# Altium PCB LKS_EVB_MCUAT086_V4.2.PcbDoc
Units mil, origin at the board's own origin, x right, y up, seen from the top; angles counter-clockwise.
Board outline 2625 x 1560 mil, 2 copper layers (Top Layer, Bottom Layer); 66 components, 80 nets, 250 pads, 95 vias.
Unrouted connection lines stored in the file: 34.
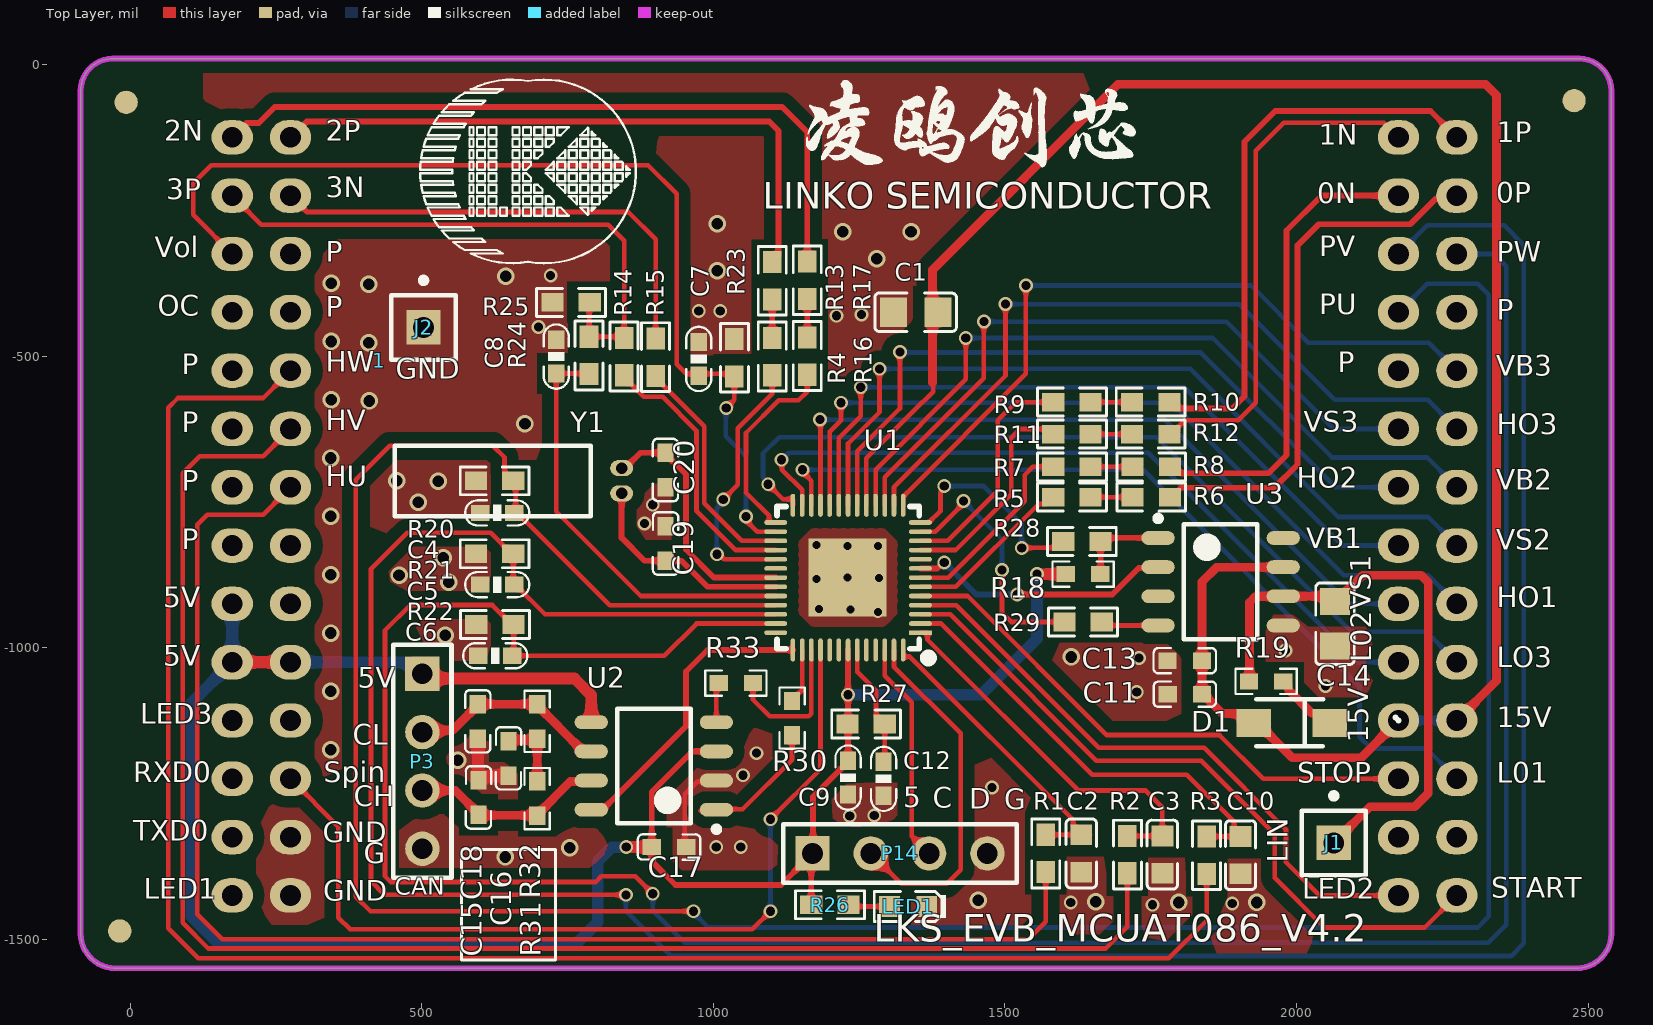
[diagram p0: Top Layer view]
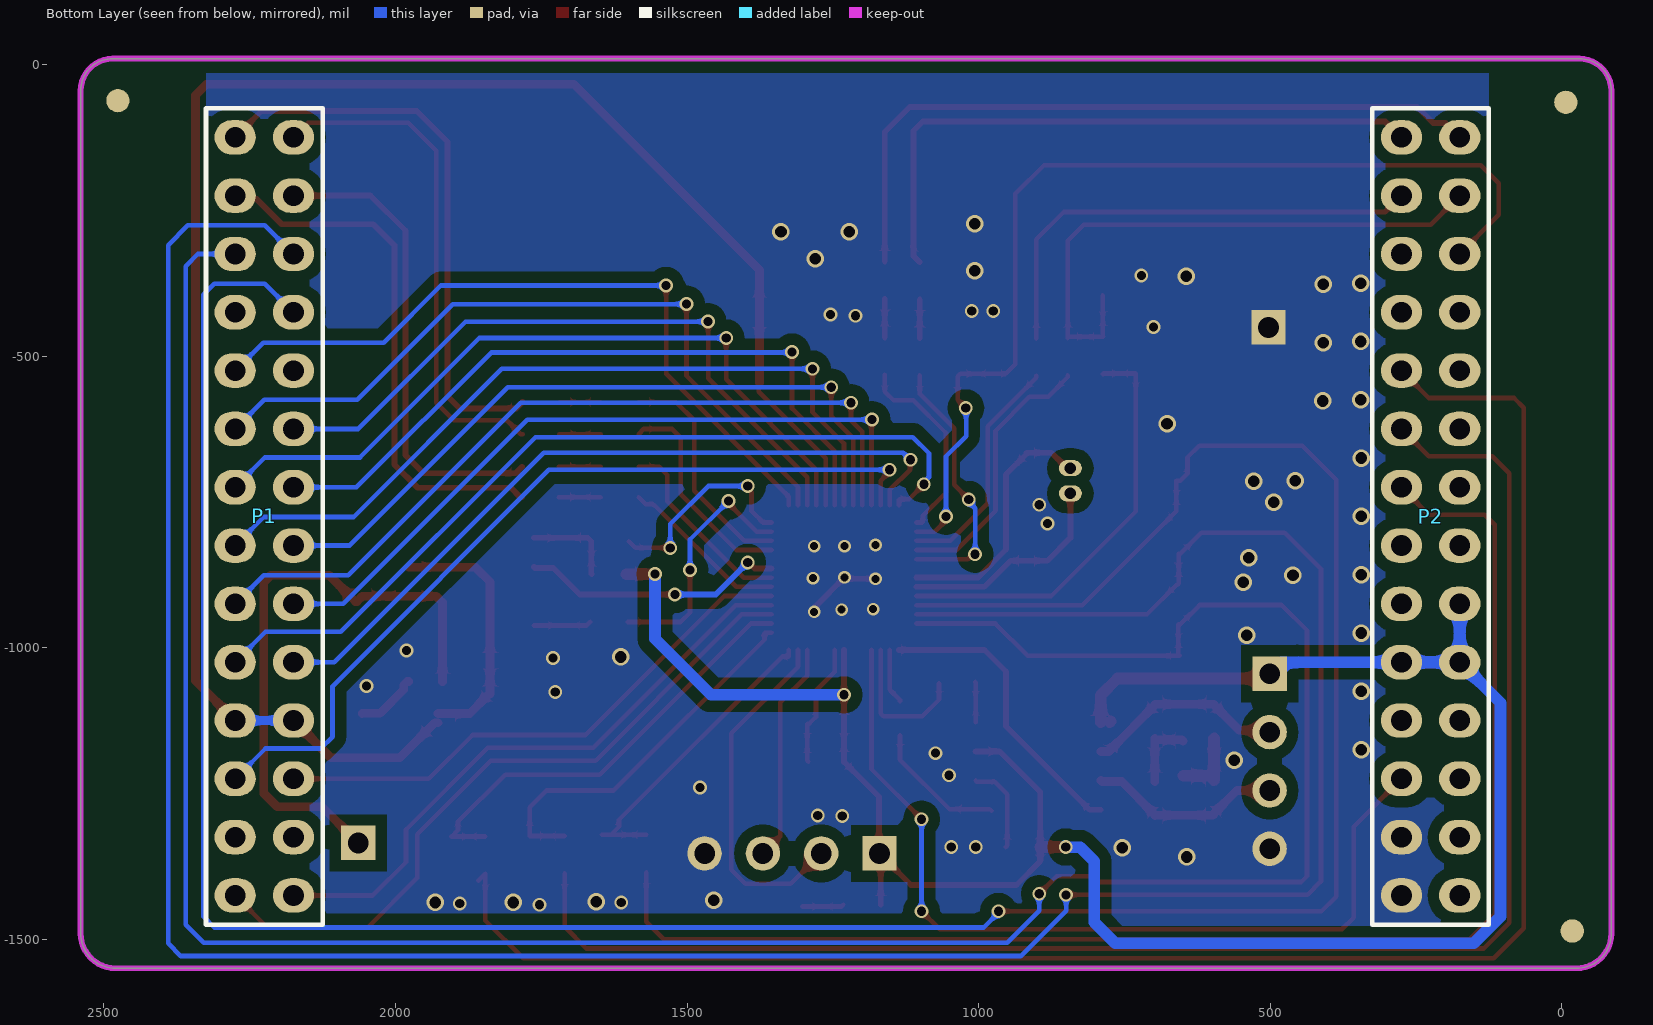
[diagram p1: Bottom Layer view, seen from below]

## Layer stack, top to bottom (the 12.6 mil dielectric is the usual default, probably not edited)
Top Solder: solder mask 0.4, Solder Resist, Dk 3.5
Top Layer: signal copper 1.4
Dielectric1: dielectric 12.6, FR-4, Dk 4.8
Bottom Layer: signal copper 1.4
Bottom Solder: solder mask 0.4, Solder Resist, Dk 3.5

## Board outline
-85,-1490 ccw(c-25,-1490) -25,-1550 2480,-1550 ccw(c2480,-1490) 2540,-1490 2540,-45 ccw(c2485,-45) 2485,10 -30,10 ccw(c-30,-45) -85,-45

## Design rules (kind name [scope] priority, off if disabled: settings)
Clearance Clearance_1 [InPolygon] p1: gap=20 ignorepadtopadclearanceinfootprint=FALSE except(0: Arc-Hole Track-Hole SMDPad-Hole THPad-Hole Via-Hole Fill-Hole Poly-Hole Region-Hole Text-Hole)
Clearance [All] p2: gap=0 ignorepadtopadclearanceinfootprint=FALSE
ComponentClearance [All] p1: gap=0 collisioncheckmode=3 verticalgap=0 showdistances=FALSE
FabricationTestpoint [(IsPad And (OnTopLayer Or OnBottomLayer))] p1: side=3 testpointundercomponent=TRUE minsize=40 maxsize=100 preferedsize=60 minholesize=0 maxholesize=40 preferedholesize=32 testpointgrid=1 allowsidetop=TRUE allowsidebottom=TRUE usegrid=TRUE gridtolerance=0.01
HoleSize [All] p1: absolutevalues=TRUE maxlimit=100 minlimit=0 maxpercent=80.000 minpercent=20.000
PolygonConnect [All] p1: connectstyle=Direct reliefconductorwidth=30 reliefentries=4 polygonreliefangle="90 Angle" airgapwidth=10
RoutingVias [All] p1: holewidth=12 width=20 viastyle="Through Hole" minholewidth=0 minwidth=10 maxholewidth=100 maxwidth=200
SilkToSolderMaskClearance SilkscreenOverComponentPads [IsPad] p1: minsilkscreentomaskgap=10 clearancetoexposedcopper=TRUE
SolderMaskExpansion [All] p1: expansion=4 istentingtop=FALSE
Width [All] p1: maxlimit=100 minlimit=7.87 preferedwidth=10
26 further rules are at their usual default settings.

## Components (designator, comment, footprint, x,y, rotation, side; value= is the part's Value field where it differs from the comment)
1 "LKS_sign" LKS_LOGO2 427,-508 r0 top
C1 "10uF/25V" 0805C 1347,-425 r180 top
C2 "10nF/16V" 0603C#1 1631,-1353 r270 top
C3 "10nF/16V" 0603C#1 1770,-1355 r270 top
C4 "1nF/16V" 0603C#2 629.41,-768.98 r180 top
C5 "1nF/16V" 0603C#2 629.41,-892 r180 top
C6 "1nF/16V" 0603C#2 626.05,-1014 r180 top
C7 "100nF/50V" 0603C#2 975,-504.95 r270 top
C8 "1nF/50V" 0603C#2 730.65,-500.91 r270 top
C9 "1uF/16V" 0603C#2 1231,-1223 r90 top
C10 "10nF/16V" 0603C#1 1904,-1356 r270 top
C11 "2.2uF/25V" "0603C _1" 1808.47,-1080 r180 top
C12 "100nF/50V" 0603C#2 1292,-1225 r270 top
C13 "100nF" "0603C _1" 1808.44,-1022.53 r180 top
C14 "1nF" 0805C 2066,-959 r270 top
C15 "30pF" "0603C _1" 597,-1257 r90 top
C16 "4.7nF/50V" "0603C _1" 649,-1190 r270 top
C17 "100nF" "0603C _1" 924,-1342 r180 top
C18 "30pF" "0603C _1" 596,-1126.47 r90 top
C19 "4.7nF/50V" "0603C _1" 918,-821.53 r90 top
C20 "4.7nF/50V" "0603C _1" 918,-695.47 r270 top
D1 "1N4148" SOD123 1992,-1129 r0 top
J1 "Socket" PIN1 2064,-1335 r0 top
J2 "Socket" PIN1 503,-451 r0 top
LED1 "LED" 0603D 1334,-1444 r0 top
P1 "Header 14X2A" "HDR 2X14 顶层" 2225,-775 r180 bottom locked
P2 "Header 14X2A" "HDR 2X14 顶层" 225,-775 r180 bottom locked
P3 "Header 4" HDR1X4 501,-1045 r270 top
P14 "Header 4" "HDR 1X4" 1170,-1353 r0 top
R1 "2K" 0603R 1570,-1353 r90 top value=K
R2 "2K" 0603R 1710,-1355 r90 top value=K
R3 "2K" 0603R 1846,-1356 r90 top value=K
R4 "20K" 0603R 1101,-501 r270 top value=K
R5 "20K" 0603R 1615,-742 r180 top value=K
R6 "20K" 0603R 1751,-742 r180 top value=K
R7 "20K" 0603R 1615,-690 r180 top value=K
R8 "20K" 0603R 1751,-690 r180 top value=K
R9 "20K" 0603R 1615,-579 r180 top value=K
R10 "20K" 0603R 1750,-579 r180 top value=K
R11 "20K" 0603R 1615,-634 r180 top value=K
R12 "20K" 0603R 1750,-634 r180 top value=K
R13 "20K" 0603R 1101,-371 r270 top value=K
R14 "1K" 0603R 847,-501 r270 top value=K
R15 "1K" 0603R 901,-502 r270 top value=K
R16 "20K" 0603R 1161,-500 r270 top value=K
R17 "20K" 0603R 1161,-370 r270 top value=K
R18 "10K" 0603R_1 1634,-874 r0 top value=K
R19 "1K" 0603R_1 1948,-1058 r180 top value=K
R20 "1K" 0603R 625,-713.95 r180 top value=K
R21 "1K" 0603R 625,-839 r180 top value=K
R22 "1K" 0603R 625.55,-960.32 r180 top value=K
R23 "1K" 0603R 1036,-503 r270 top value=K
R24 "1K" 0603R 786.65,-498.91 r90 top value=K
R25 "10R" 0603R 756,-408 r180 top value=K
R26 "3.3K" 0603R 1200,-1441 r180 top value=330
R27 "20K" 0603R 1262,-1131 r0 top value=K
R28 "10R" 0603R 1632,-818 r180 top value=K
R29 "10R" 0603R 1634,-956 r180 top value=K
R30 "10R" 0603R_1 1135,-1121 r270 top value=K
R31 "60R/1%" 0603R_1 698,-1259 r90 top value=K
R32 "60R/1%" 0603R_1 698,-1126.47 r90 top value=K
R33 "10R" 0603R_1 1038.51,-1061 r180 top value=K
U1 "LKS32AT086N8Q8" QFN52 1355.02,-974.49 r180 top
U2 "SIT1051T/3" SOP-8N 898,-1203 r180 top
U3 "SIT1027Q" SOP-8N 1870,-887 r0 top
Y1 "WTL3T45412LZ" DT-38 579,-714 r0 top

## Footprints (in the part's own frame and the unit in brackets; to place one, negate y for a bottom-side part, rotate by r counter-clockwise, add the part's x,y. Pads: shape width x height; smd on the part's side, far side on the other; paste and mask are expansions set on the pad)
0603C#1 [mm]
  rect 0.9x0.95 smd: 1(-0.813,0) 2(0.813,0)
  silkscreen extent -1.5,-0.66 1.5,0.66, body extent -0.8,-0.4 0.8,0.4, height 0.45
0603C#2 [mm] "电?"
  rect 0.8x0.7 smd: 1(-0.737,0) 2(0.738,0)
  silkscreen extent -1.4,-0.55 1.4,0.55, body extent -0.8,-0.41 0.8,0.41, height 0.81
"0603C _1" [mm]
  rect 0.8x0.7 smd: 1(-0.75,0) 2(0.75,0)
  silkscreen extent -1.36,-0.56 1.36,0.55, body extent -0.8,-0.41 0.8,0.41, height 0.81
0603D [mm]
  rect 0.9x0.9 smd: 1(-0.813,0) 2(0.813,0)
  silkscreen extent -1.47,-0.66 1.65,0.66
0603R [mil]
  rect 38x32 smd: 1(-32,0) 2(32,0)
  silkscreen extent -59,-24 59,24, body extent -31,-16 32,16, height 16
0603R_1 [mm]
  rect 0.8x0.7 smd: 1(-0.75,0) 2(0.75,0)
  silkscreen extent -1.33,-0.55 1.33,0.55, body extent -0.8,-0.4 0.8,0.4, height 0.4
0805C [mil]
  rect 46x51.18 smd: 1(-38,0) 2(38,0)
  silkscreen extent -70,-33 70,33, body extent -40,-25 38,25, height 22
DT-38 [mm] "CRYSTAL 晶?"
  oval 1x0.7 hole 0.5 paste+0 mask+0: 1(6.7,0.55) 2(6.7,-0.55)
  silkscreen extent -3.17,-1.55 5.36,1.52, body extent -3.2,-1.85 6.73,1.85, height 0.25
HDR1X4 [mm] "Connector; Header; 4 Position"
  rect 1.5x1.5 hole 0.9: 1(0,0)
  round 1.5 hole 0.9: 2(2.54,0) 3(5.08,0) 4(7.62,0)
  silkscreen extent -1.27,-1.27 8.89,1.27
"HDR 1X4" [mm] "排针-单 2.54"
  rect 1.5x1.5 hole 0.9: 1(0,0)
  round 1.5 hole 0.9: 2(2.54,0) 3(5.08,0) 4(7.62,0)
  silkscreen extent -1.27,-1.27 8.89,1.27, body extent -1.27,-1.27 8.89,1.27, height 8.5
"HDR 2X14 顶层" [mm] "双排针 2.54mm 顶层"
  oval 1.8x1.5 hole 0.9: 1(1.27,16.51) 2(1.27,13.97) 3(1.27,11.43) 4(1.27,8.89) 5(1.27,6.35) 6(1.27,3.81) 7(1.27,1.27) 8(1.27,-1.27) 9(1.27,-3.81) 10(1.27,-6.35) 11(1.27,-8.89) 12(1.27,-11.43) 13(1.27,-13.97) 14(1.27,-16.51) 15(-1.27,16.51) 16(-1.27,13.97) 17(-1.27,11.43) 18(-1.27,8.89) 19(-1.27,6.35) 20(-1.27,3.81) 21(-1.27,1.27) 22(-1.27,-1.27) 23(-1.27,-3.81) 24(-1.27,-6.35) 25(-1.27,-8.89) 26(-1.27,-11.43) 27(-1.27,-13.97) 28(-1.27,-16.51)
  silkscreen extent -2.54,-17.78 2.54,17.78, body extent -2.54,-17.78 2.54,17.78, height 8.5
LKS_LOGO2 [mil] "标?"
  silkscreen extent 70,167 440,482
PIN1 [mm] "Connector; Plug"
  rect 1.5x1.5 hole 0.9: 1(0,0)
  silkscreen extent -1.4,-1.4 1.4,2.17
QFN52 [mm]
  rect 3.4x3.4 smd: 0(3.175,-2.413)
  rect 1x0.2 smd: 1(0,0)
  oval 1x0.2 smd: 2(0,-0.4) 3(0,-0.8) 4(0,-1.2) 5(0,-1.6) 6(0,-2) 7(0,-2.4) 8(0,-2.8) 9(0,-3.2) 10(0,-3.6) 11(0,-4) 12(0,-4.4) 13(0,-4.8) 27(6.3,-4.8) 28(6.3,-4.4) 29(6.3,-4) 30(6.3,-3.6) 31(6.3,-3.2) 32(6.3,-2.8) 33(6.3,-2.4) 34(6.3,-2) 35(6.3,-1.6) 36(6.3,-1.2) 37(6.3,-0.8) 38(6.3,-0.4) 39(6.3,0)
  oval 0.2x1 smd: 14(0.75,-5.55) 15(1.15,-5.55) 16(1.55,-5.55) 17(1.95,-5.55) 18(2.35,-5.55) 19(2.75,-5.55) 20(3.15,-5.55) 21(3.55,-5.55) 22(3.95,-5.55) 23(4.35,-5.55) 24(4.75,-5.55) 25(5.15,-5.55) 26(5.55,-5.55) 40(5.55,0.75) 41(5.15,0.75) 42(4.75,0.75) 43(4.35,0.75) 44(3.95,0.75) 45(3.55,0.75) 46(3.15,0.75) 47(2.75,0.75) 48(2.35,0.75) 49(1.95,0.75) 50(1.55,0.75) 51(1.15,0.75) 52(0.75,0.75)
  silkscreen extent -0.46,-5.5 6.25,1.21
SOD123 [mm] "SOD-123; 2 Leads; Body 2.7 x 1.6 mm, (LxW)"
  rect 1.5x1.22 smd: 1(-1.65,0) 2(1.65,0)
  silkscreen extent -1.55,-1.03 1.38,1.02, body extent -1.93,-0.82 1.93,0.87, height 0.92
SOP-8N [mm]
  oval 1.45x0.6 smd: 1(-2.725,1.905) 2(-2.725,0.635) 3(-2.725,-0.635) 4(-2.725,-1.905) 5(2.725,-1.905) 6(2.725,-0.635) 7(2.725,0.635) 8(2.725,1.905)
  silkscreen extent -2.85,-2.5 1.6,2.88, body extent -2,-2.5 2,2.5, height 1.7

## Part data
C1 C11 C13 C14 C15 C16 C17 C18 C19 C20: library part Capacitor, "Capacitor --贴片电容"
C2 C3 C4 C5 C6 C10: library part CAP, "Capacitor"
C7 C8 C9 C12: library part C, "Capacitor"
D1: library part Diode, "Default Diode", PackageDocument=Sep-1996
LED1: "LED_Light"
P1 P2: "Header, 14-Pin, Dual row"
P3 P14: "Header, 4-Pin"
R1 R2 R3 R4 R5 R6 R7 R8 R9 R10 R11 R12 R13 R14 R15 R16 R17 R18 R19 R20 R21 R22 R23 R24 R25 R26 R27 R28 R29 R30 R31 R32 R33: library part Res, "Resistor"
U1: "车规芯片"
U2: "SIT芯力特CAN芯片  sop-8"
U3: library part SIT1021T, "SIT芯力特LIN芯片  SOP-8"
Y1: library part CMP-27762-006068-1, "CRYSTAL 32.7680KHZ 12.5PF TH", Case/Package=Radial, ESR (Equivalent Series Resistance)=50kR, Frequency=32.768kHz, Frequency Stability=-0.034ppm, Frequency Tolerance=20ppm, Load Capacitance=12.5pF, Manufacturer=Abracon, Manufacturer Part Number=AB26TRB-32.768KHZ-T, Max Operating Temperature=85°C, Min Operating Temperature=-40°C, Operating Frequency="32.768 kHz", Package Quantity=500

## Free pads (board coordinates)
  round 40 all layers, no hole: 5(-18,-1486) 5(-7,-65) 5(2476,-62)

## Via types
v1: diameter 23.62, hole 15.75, Top Layer to Bottom Layer, 52 vias
v2: diameter 30, hole 20, Top Layer to Bottom Layer, 34 vias
v3: diameter 21.65, hole 13.78, Top Layer to Bottom Layer, 9 vias

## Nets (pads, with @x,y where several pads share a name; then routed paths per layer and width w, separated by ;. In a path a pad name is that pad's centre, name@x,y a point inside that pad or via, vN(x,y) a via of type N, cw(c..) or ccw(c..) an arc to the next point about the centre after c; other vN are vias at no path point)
+5V: C9.2 C17.2 P2.9 P2.10 P2.24 P3.1 P14.1 R18.1 R26.2 R27.1 U1.46 U2.3 U2.5 | length 3860.5
  Top Layer w10: U2.3 964,-1178 894.47,-1247.53 C17.2 894.47,-1366.47 935,-1407 1116,-1407 P14.1 ; R26.2 1168,-1355 P14.1 ; U1.46 v1(1231,-1081) C9.2 1231,-1195.91 1171,-1255.91 1171,-1352 P14.1
  Top Layer w20: P2.10 P2.24 P2.24@275,-1018 ; P3.1 509,-1053 762,-1053 790.72,-1081.72 U2.5 ; U2.5@773.29,-1126.33 U2.5@774.96,-1128 ; v1(850.56,-1341.86) v1(850.56,-1341.86) 894.4,-1341.93 C17.2 ; v1(1555,-874) R18.1
  Bottom Layer w20: P2.9 P2.10 ; P3.1 481,-1025 P2.24 P2.10 ; v1@851.26,-1340.19 851.26,-1341.17 849.87,-1342.55 826.01,-1342.55 802,-1366.57 802,-1471 766,-1507 151,-1507 105,-1461 105,-1095 P2.10 ; v1(1231,-1081) 1459,-1081 1555,-985 v1(1555,-874)
+15V: C1.1 C11.1 C13.1 D1.1 P1.11 P1.25 U1.18 U3.7 | length 3502.8
  Top Layer w8: U1.18 1262.5,-675.5 1343,-595 1377,-561 1377,-545.65
  Top Layer w15: 1376,-545.65 1376,-352 1694,-34 2324,-34 2343,-53 2343,-1057 P1.25 ; D1.1@1927,-1113 1872.97,-1113 1839.97,-1080 C11.1 1838,-887 1863,-862 U3.7 ; D1.1 1932.55,-1129 1992.55,-1189 2111,-1189 P1.11
  Bottom Layer w15: P1.11 P1.25
CAN_RX: R33.1 U1.42 | length 251.5
  Top Layer w8: R33.1 1068.04,-1089.54 1096.5,-1118 1163.32,-1118 1168.01,-1113.31 U1.42
CAN_TX: R30.1 U1.41 | length 94.6
  Top Layer w8: R30.1 1135,-1089.5 1152.26,-1072.24 U1.41
CANH: C15.1 P3.3 R31.1 U2.7 | length 335.1
  Top Layer w15: P3.3 557.44,-1245 597,-1284.56 C15.1 598,-1287.53 697,-1287.53 R31.1 698,-1286.56 754.91,-1229.65 789.07,-1229.65 U2.7
CANL: C18.2 P3.2 R32.2 U2.6 | length 350
  Top Layer w15: P3.2@501,-1149 P3.2 504.11,-1141.89 553.03,-1141.89 596,-1098.91 C18.2 R32.2 698,-1098.91 772.33,-1173.25 772.33,-1174.02 776.32,-1178 U2.6
GND: C1.2 C2.2 C3.2 C4.2 C5.2 C6.2 C7.1 C8.1 C9.1 C10.2 C11.2 C12.2 C13.2 C14.2 C15.2 C16.2 C17.1 C18.1 C19.2 C20.2 J2.1 LED1.2 P2.27 P2.28 P3.4 P14.4 R20.2 R21.2 R22.2 R23.1 R25.2 U1.0 U2.2 U3.5 | length 418.6
  Top Layer w8: C17.1 951,-1339.47 951,-1251.69 972.78,-1229.9 1003.38,-1229.9 U2.2
  Top Layer w10: v3(1177,-882) 1227.5,-882 v3(1230.02,-879.49) 1282,-931.47 v3(1282,-938.74)
  Top Layer w20: C18.1 596.5,-1156.5 596.5,-1226.97 C15.2 597,-1225.5 602.98,-1219.53 C16.2
  other v1: 1753,-1441 1889.98,-1438.88 1613,-1437 1005,-1342 1047,-1342 1234,-1289 1276,-1288 1478,-1240 1051,-1219 1074,-1181 1726,-1076 2050,-1066 1730,-1018 1981,-1005 882,-787 896,-755 700,-450 1211,-431 1254,-429 975,-423 1012,-423 721,-362
  other v2: 1798,-1437 1932,-1437 1656,-1436 1454,-1433 643,-1359 754,-1343 562,-1193 344,-1175 344,-1075 1614,-1016 540,-979 344,-975 546,-888 461,-876 344,-875 537,-846 344,-775 494,-751 528,-715 456.95,-714 344,-675 677,-616 410,-577 345,-575 409,-477 345,-475 409,-377 345,-375 644,-363 1007,-354 1280,-333 1222,-287 1339,-287 1007,-273
  other v3: 1235,-935 1181,-934 1284,-881 1230,-826 1282,-826 1177,-824
GND0: P2.16 R15.1 | length 827.1
  Top Layer w8: P2.16 303,-253 854,-253 901,-300 R15.1
HALL_U: C2.1 R1.2 U1.52 | length 525
  Top Layer w8: U1.52 1325.49,-1014.51 1326.34,-1015.36 1336.84,-1015.36 1616.81,-1295.33 1616.81,-1307.28 1630.52,-1321 C2.1@1646,-1321 ; R1.2 C2.1@1630.02,-1321
HALL_V: C3.1 R2.2 U1.1 | length 653.7
  Top Layer w8: U1.1 1366.33,-974.49 1367.25,-975.41 1367.25,-986.72 1625.53,-1245 1741,-1245 1770,-1274 C3.1 ; R2.2 C3.1@1769.02,-1323
HALL_W: C10.1 R3.2 U1.2 | length 765.5
  Top Layer w8: U1.2 1390.74,-958.74 1650,-1218 1812,-1218 1892.97,-1298.97 1892.97,-1312.97 C10.1 ; R3.2 C10.1@1903.02,-1324
HO1: P1.23 U1.22 | length 1383
  Top Layer w8: U1.22 1199.5,-629.5 1219,-610 v1(1219,-580)
  Bottom Layer w8: v1(1219,-580) 1785,-580 2081,-876 2226,-876 P1.23
HO2: P1.7 U1.19 | length 1244
  Top Layer w8: U1.19 1246.75,-663.25 1320,-590 v1(1320,-493)
  Bottom Layer w8: v1@1320,-494 1836,-494 2067,-725 P1.7
HO3: P1.20 U1.15 | length 1286.8
  Top Layer w8: U1.15 1309.74,-725.26 1501,-534 v1(1501,-411)
  Bottom Layer w8: v1(1501,-411) 1902,-411 2066,-575 2225,-575 P1.20
HU: P2.21 R1.1 | length 2424.7
  Top Layer w8: P2.21 228,-772 132,-772 115,-789 115,-1457 158,-1500 1540,-1500 1570,-1470 R1.1
HV: P2.20 R2.1 | length 2733
  Top Layer w8: P2.20 228,-672 119,-672 90,-701 90,-1472 134,-1516 1673,-1516 1710,-1479 R2.1
HW: P2.19 R3.1 | length 3054.9
  Top Layer w8: P2.19 228,-572 82,-572 65,-589 65,-1481 117,-1533 1781,-1533 1846,-1468 R3.1 R3.1@1858,-1400
INH: U3.8
LED1: P2.14
LED2: P1.14 U1.4 | length 1059
  Top Layer w8: U1.4 1416.24,-927.24 1661,-1172 1842,-1172 1982,-1312 1982,-1368 2039,-1425 P1.14
LED3: P2.11
LIN: C14.1 J1.1 R19.2 U3.6 | length 1032.9
  Top Layer w15: R19.2@1919.47,-1058 1919.47,-922.53 1930,-912 U3.6 2057,-912 C14.1 2068.59,-921 2113.59,-876 2214,-876 2226,-888 2226,-1250 2203,-1273 2126,-1273 J1.1
LO1: P1.26 U1.24 | length 1459.7
  Top Layer w8: v1(1153,-695) 1153,-698.66 1168.01,-713.67 U1.24
  Bottom Layer w8: v1(1153,-695) 1737,-695 2108,-1066 2108,-1153 2128,-1173 2223,-1173 P1.26
LO2: P1.10 U1.25 | length 1304.3
  Top Layer w8: v1(1117,-678) 1117.7,-678.7 1117.7,-694.97 1152.26,-729.54 U1.25
  Bottom Layer w8: v1(1117,-678) 1117.5,-678 1129.5,-666 1746,-666 2105,-1025 P1.10
LO3: P1.24 U1.26 | length 1481.1
  Top Layer w8: v1(1094,-720) 1119.46,-745.46 1135.66,-745.46 1136.51,-746.31 U1.26
  Bottom Layer w8: v1(1094,-720) 1094,-716.31 1085.19,-707.5 1085.19,-666.81 1113,-639 1760,-639 2094,-973 2223,-973 P1.24
NetC16_1: C16.1 R31.2 R32.1 | length 124.3
  Top Layer w15: C16.1 651.24,-1158.24 695.76,-1158.24 R32.1 R31.2
NetD1_2: D1.2 R19.1 | length 106.6
  Top Layer w15: R19.1 1979.5,-1058 1985.78,-1064.28 1985.78,-1071.82 2026.44,-1112.48 2056.41,-1112.48 D1.2@2056.92,-1113
NetLED1_1: LED1.1 R26.1 | length 71.2
  Top Layer w8: R26.1 1235,-1444 LED1.1
NetR4_1: R4.1 R13.2 | length 66
  Top Layer w10: R4.1 R13.2
NetR5_1: R5.1 R6.2 | length 72
  Top Layer w8: R5.1@1648,-742 R6.2@1720,-742
NetR7_1: R7.1 R8.2 | length 72
  Top Layer w8: R7.1@1648,-690 R8.2@1720,-690
NetR9_1: R9.1 R10.2 | length 71
  Top Layer w8: R9.1@1648,-579 R10.2@1719,-579
NetR11_1: R11.1 R12.2 | length 71
  Top Layer w8: R11.1@1648,-634 R12.2@1719,-634
NetR16_1: R16.1 R17.2 | length 66
  Top Layer w10: R16.1 R17.2
NetR28_2: R28.2 U1.13 | length 368.8
  Top Layer w8: U1.13 1369.78,-785.51 1389.48,-765.81 1389.48,-733.75 1396,-727.23 v1(1396,-723) ; v1@1531.99,-826.01 v1(1529,-829) 1589,-829 R28.2
  Bottom Layer w8: v1(1396,-723) 1464,-723 1529,-788 v1(1529,-829)
NetR29_2: R29.2 U1.12 | length 430.6
  Top Layer w8: U1.12 1380.74,-801.26 1426.01,-755.99 1426.01,-751.66 v1(1429,-748.67) ; v1(1495,-867) 1495,-940 1511,-956 R29.2
  Bottom Layer w8: v1(1429,-748.67) 1495,-814.67 v1(1495,-867)
NetR30_2: R30.2 U2.1 | length 234.9
  Top Layer w8: U2.1@978,-1280 980.99,-1277.01 1049.99,-1277.01 1135,-1192 R30.2
NetR33_2: R33.2 U2.4 | length 69.2
  Top Layer w8: U2.4 1005.28,-1059.47 R33.2@1005.76,-1059
NRST: C12.1 R27.2 U1.47 | length 214.1
  Top Layer w8: U1.47 1246.75,-1041.75 1279,-1074 1279,-1119 1291,-1131 R27.2 1294,-1194 C12.1
OC: C8.2 R24.1 U1.35 | length 729.4
  Top Layer w8: R24.1 785.71,-529.96 C8.2 730.65,-766.65 875.5,-911.5 U1.35
OPA0_IN: R16.2 U1.27 | length 344.2
  Top Layer w8: U1.27 1096.49,-785.51 1095.64,-784.66 1095.64,-774.16 1056,-734.53 1056,-632 1112,-576 1146,-576 1161,-561 R16.2
OPA0_IP: R4.2 U1.31 | length 450.7
  Top Layer w8: v1(1006.11,-840) 1010.34,-840 1018.84,-848.5 U1.31 ; v1(1017,-746) 1042,-721 1042,-624 1101,-565 R4.2
  Bottom Layer w8: v1(1006.11,-840) 1006.11,-761.11 1017,-750.23 v1(1017,-746)
OPA1_IN: R15.2 U1.29 | length 402.3
  Top Layer w8: R15.2 901,-537 984.5,-620.5 984.5,-752.5 1049.01,-817.01 U1.29
OPA1_IP: R14.2 U1.30 | length 466.2
  Top Layer w8: R14.2 847,-536 881,-570 913,-570 971,-628 971,-765 1038.76,-832.76 U1.30
OPA2_IN: R11.2 U1.10 | length 374.6
  Top Layer w8: U1.10 1415.24,-832.76 1511,-737 1511,-640 1526,-625 1574,-625 R11.2
OPA2_IP: R9.2 U1.11 | length 397.5
  Top Layer w8: U1.11 1401.99,-817.01 1488,-731 1488,-610 1519,-579 R9.2
OPA3_IN: R7.2 U1.7 | length 333
  Top Layer w8: U1.7 1403,-880 1534,-749 1534,-704 1548,-690 R7.2
OPA3_IP: R5.2 U1.6 | length 291.7
  Top Layer w8: U1.6 1415.75,-895.75 1555,-756.5 1556,-756.5 1558.5,-754 1571,-754 R5.2
OSC_IN: C20.1 U1.33 Y1.1 | length 440.5
  Top Layer w10: Y1.1 848.68,-692.35 875.09,-665.95 C20.1 918,-667.91 953,-702.91 953,-831.87 1001.13,-880 U1.33
OSC_OUT: C19.1 U1.34 Y1.2 | length 375.1
  Top Layer w10: Y1.2 842.78,-811.78 882.05,-851.05 C19.1 945.31,-851.05 990,-895.75 U1.34
P2.12: U1.39
PGND: P2.2 R14.1 R24.2 R25.1 | length 1003.2
  Top Layer w8: P2.2 225,-275 820,-275 847,-302 R14.1 844.91,-466.91 R24.2@786.84,-466.91 ; R24.2 R24.2@786.84,-466.91 ; R24.2@786.75,-467 R24.2@786.84,-466.91 ; R25.1@787,-396 787,-466.75 R24.2@786.84,-466.91
PGND0: P1.2 R8.1 | length 819.4
  Top Layer w10: R8.1 1794,-701 1952,-701 1983,-670 1983,-284.72 2042.72,-225 P1.2
PGND1: P1.1 R12.1 | length 877.6
  Top Layer w8: R12.1 1785,-634 1809,-610 1900,-610 1930,-580 1930,-148 1978,-100 2150,-100 P1.1
PGND2: P2.1 R17.1 | length 1247.4
  Top Layer w10: P2.1 199.53,-100.47 220.53,-100.47 248,-73 1118,-73 1161,-116 R17.1
PU: C4.1 P1.4 R20.1 U1.36 | length 4842.7
  Top Layer w8: v1(966,-1452.11) 412.11,-1452.11 387,-1427 387,-712 445,-654 622,-654 642,-674 642,-701.95 654,-713.95 R20.1 660.96,-713.95 660.96,-765.96 822.24,-927.24 U1.36
  Bottom Layer w8: v1(966,-1452.11) 966,-1455 991,-1480 2311,-1480 2330,-1461 2330,-395 2311,-376 2224,-376 P1.4
PV: C5.1 P1.3 R21.1 U1.37 | length 4845.2
  Top Layer w8: v1(850,-1424) 436,-1424 413,-1401 413,-865 475,-803 618,-803 654,-839 R21.1 657,-890.59 C5.1 660.38,-892 711.37,-942.99 U1.37
  Bottom Layer w8: v1(850,-1424) 850,-1451 928,-1529 2368,-1529 2390,-1507 2390,-310 2356,-276 2224,-276 P1.3
PW: C6.1 P1.17 R22.1 U1.38 | length 4434.6
  Top Layer w8: v1(896,-1422) 866,-1392 808,-1392 798,-1402 447,-1402 437,-1392 437,-970 480,-927 621.23,-927 654.55,-960.32 R22.1 657.55,-1011.51 C6.1 916,-1014 971.26,-958.74 U1.38
  Bottom Layer w8: v1@896.31,-1422 896.31,-1451.31 951,-1506 2329,-1506 2360,-1475 2360,-346 2339,-325 P1.17
RXD0: P2.12
RXD1: R18.2 R28.1 U3.1 | length 157.4
  Top Layer w9.45: R18.2 1664,-873.53 R28.1 1670,-812 U3.1
SLP_N: U1.8 U3.2 | length 454.2
  Top Layer w10: U1.8 1383.85,-864.25 1394.1,-854 v1(1396,-854) ; v1(1521,-909) 1684,-909 1729.53,-863.47 1761.25,-863.47 U3.2
  Bottom Layer w10: v1(1396,-854) 1451,-909 v1(1521,-909)
SPIN: P2.26 U1.43 | length 1517.8
  Top Layer w8: P2.26 357,-1307 357,-1463 377,-1483 1067,-1483 v1(1098,-1452) ; v1(1097.79,-1294.21) 1183.76,-1208.24 U1.43
  Bottom Layer w8: v1(1097.79,-1294.21) 1097.9,-1294.31 1097.9,-1451.9 v1(1098,-1452)
START1: P1.28 U1.3 | length 1209.1
  Top Layer w8: U1.3 1405.99,-942.99 1443,-980 1657,-1194 1837,-1194 1963,-1320 1963,-1395 2048,-1480 2220,-1480 P1.28
STB: U1.40 U2.8 | length 514.3
  Top Layer w10: U2.8 810,-1278 953,-1135 953,-1041 989.98,-1004.02 U1.40
STOP1: P1.12 U1.5 | length 949.8
  Top Layer w8: U1.5 1436.5,-911.5 1675,-1150 1868,-1150 1943,-1225 P1.12
SWCLK: P14.2 U1.51 | length 609.8
  Top Layer w8: P14.2 1322,-1405 1400,-1405 1424,-1381 1424,-1147 1309.74,-1032.74 U1.51
SWDIO: P14.3 U1.50 | length 380.5
  Top Layer w8: U1.50 1293.99,-1047.99 1340,-1094 1340,-1323 P14.3
TXD0: P2.13
TXD1: R29.1 U3.4 | length 99.2
  Top Layer w8: R29.1 1672,-962 U3.4
UP-: P2.15 R13.1 | length 1084.4
  Top Layer w10: P2.15 275.69,-125 302.69,-98 1096,-98 1112,-114 1112,-328 R13.1
VB1: P1.8 U1.21 | length 1252.8
  Top Layer w8: U1.21 1215.25,-640.75 1252.75,-603.25 v1(1252.75,-553.44)
  Bottom Layer w8: v1(1252.75,-553.44) 1807.44,-553.44 2079,-825 P1.8
VB2: P1.21 U1.17 | length 1299.1
  Top Layer w8: U1.17 1278.24,-694.76 1433,-540 v1(1433,-469)
  Bottom Layer w8: v1(1433,-469) 1856,-469 2061,-674 2224,-674 P1.21
VB3: P1.19 U1.14 | length 1263.7
  Top Layer w8: U1.14 1325.49,-741.22 1536,-530.71 v1(1536,-379)
  Bottom Layer w8: v1(1536,-379) 1922,-379 2020,-477 2227,-477 P1.19
VOL_ADC: C7.2 P2.3 R23.2 U1.28 | length 1736.9
  Top Layer w8: P2.3 108,-258 108,-204 139,-173 888,-173 937,-222 937,-514.19 953.35,-530.54 1031.54,-530.54 R23.2 1036,-575 v1(1022,-589) ; v1(1056,-775) 1058.99,-777.99 1058.99,-784.95 1075.3,-801.26 U1.28
  Bottom Layer w8: v1(1022,-589) 1021.5,-589.5 1021.5,-637.5 1056,-672 v1(1056,-775)
VP-: P1.15 R10.1 | length 983.1
  Top Layer w10: R10.1 1793,-590 1890,-590 1911,-569 1911,-132.54 1963.54,-80 2230,-80 P1.15
VS1: P1.9 U1.23 | length 1270.2
  Top Layer w8: v1(1183,-609) 1183.76,-609.76 U1.23
  Bottom Layer w8: v1(1183,-609) 1774,-609 2090,-925 P1.9
VS2: P1.22 U1.20 | length 1371.9
  Top Layer w8: U1.20 1231,-650 1285,-596 v1(1285,-522)
  Bottom Layer w8: v1(1285,-522) 1818,-522 2072,-776 2226,-776 P1.22
VS3: P1.6 U1.16 | length 1172.6
  Top Layer w8: U1.16 1293.99,-708.01 1464,-538 v1(1464,-441)
  Bottom Layer w8: v1(1464,-441) 1880,-441 2064,-625 P1.6
WAKE_N: U3.3
WP-: P1.16 R6.1 | length 926.4
  Top Layer w10: R6.1 1786,-742 1802,-726 1962,-726 2002,-686 2002,-310 2038,-274 2195,-274 2238.01,-230.99 2269.01,-230.99 P1.16
pads on no net: P1.5 P1.13 P1.18 P1.27 P2.4 P2.5 P2.6 P2.7 P2.8 P2.17 P2.18 P2.22 P2.23 P2.25 U1.9 U1.32 U1.44 U1.45 U1.48 U1.49

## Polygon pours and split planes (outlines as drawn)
GND on Bottom Layer "GND_L02_P000" (solid, remove dead copper, pour order 0): 125,-1550 2325,-1550 2325,10 125,10
GND on Top Layer "GND_L01_P002" (solid, remove dead copper, pour order 2): 125,-1550 2325,-1550 2325,10 125,10

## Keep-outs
Keep-Out Layer:
  the board outline again, w10

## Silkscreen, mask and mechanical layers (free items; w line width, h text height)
Top Overlay:
  drawing of 12 lines, arcs and shapes, not listed
  text "2N" at 58,-143 h60
  text "2P" at 335,-142.59 h60
  text "1P" at 2343.06,-145 h60
  text "1N" at 2038.03,-150 h60
  text "3N" at 334.94,-240 h60
  text "3P" at 62,-243 h60
  text "0P" at 2343,-249 h60
  text "0N" at 2035.31,-250 h60
  text "PV" at 2038.81,-341 h60
  text "Vol" at 42,-343 h60
  text "P" at 335,-349.98 h60
  text "PW" at 2343.06,-350 h60
  text "PU" at 2039.25,-440 h60
  text "OC" at 47,-443 h60
  text "P" at 335,-445 h60
  text "P" at 2343.06,-450 h60
  text "HW" at 335,-539 h60
  text "P" at 2071,-540 h60
  text "P" at 88,-543 h60
  text "VB3" at 2343,-546 h60
  text "GND" at 455,-551 h60
  text "HV" at 335,-639 h60
  text "VS3" at 2012.73,-642 h60
  text "P" at 88,-643 h60
  text "HO3" at 2343.06,-646 h60
  text "HU" at 335,-735 h60
  text "HO2" at 2000.52,-738 h60
  text "VB2" at 2343,-741 h60
  text "P" at 88,-743 h60
  text "VB1" at 2016.72,-842 h60
  text "P" at 88,-843 h60
  text "VS2" at 2343,-844 h60
  text "VS1" at 2139,-935 h60 r90
  text "5V" at 57,-943 h60
  text "HO1" at 2343.06,-943 h60
  text "L02" at 2140,-1025 h60 r90
  text "5V" at 57,-1043 h60
  text "LO3" at 2343.06,-1046 h60
  text "5V" at 390.49,-1080.63 h60
  text "LED3" at 16.99,-1143 h60
  text "15V" at 2343.06,-1149 h60
  text "15V" at 2135,-1163 h60 r90
  text "CL" at 382,-1179 h60
  text "RXD0" at 4.89,-1243 h60
  text "Spin" at 332,-1243 h60
  text "STOP" at 2001,-1244 h60
  text "L01" at 2343.06,-1244 h60
  text "CH" at 383,-1284 h60
  text "5" at 1326,-1286 h60
  text "C" at 1376,-1287 h60
  text "D" at 1439,-1288 h60
  text "G" at 1499,-1289 h60
  text "TXD0" at 5,-1343 h60
  text "GND" at 330,-1346 h60
  text "LIN" at 1997,-1369 h60 r90
  text "G" at 400.63,-1381.59 h60
  text "CAN" at 454.05,-1434.54 h50
  text "START" at 2334,-1441 h60
  text "LED1" at 23.26,-1443 h60
  text "LED2" at 2010,-1443 h60
  text "GND" at 331.06,-1446 h60
  text "LKS_EVB_MCUAT086_V4.2" at 1275,-1520 h80
Top Solder:
  circle w78: c2476,-62 r17
  circle w78: c-7,-65 r17
  circle w78: c-18,-1486 r17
